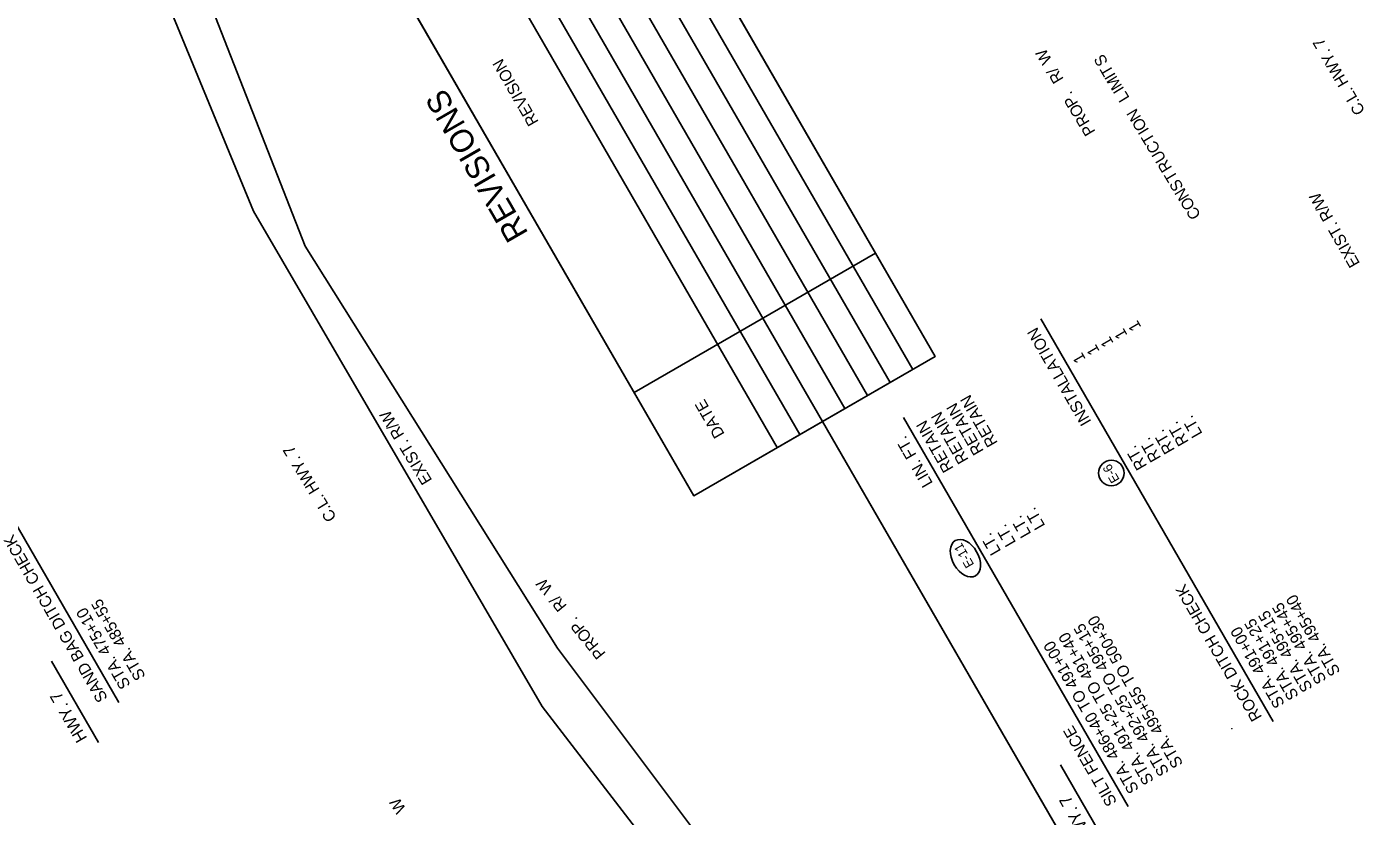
# Model space of a CAD drawing. Extents: x 956270 to 957915, y 1920520 to 1922423.
# Drawn here: x 956617 to 957310, y 1921329 to 1921739 of the extents above; entities that cross this region are included whole.
import ezdxf

# ---------------------------------------------------------------- set-up
doc = ezdxf.new("R2010")
doc.units = 0
for name, color, linetype in [('1', 7, 'Continuous'), ('44', 7, 'Continuous'), ('Default', 7, 'Continuous'), ('NO PLOT', 7, 'Continuous'), ('R_Draft', 7, 'Continuous'), ('S_MSC_PT_SYM', 7, 'Continuous')]:
    doc.layers.add(name, color=color, linetype=linetype)

msp = doc.modelspace()

# ---------------------------------------------------------------- linework, layer by layer
at = {"layer": '1'}
msp.add_line((957172.25, 1921286.08), (957029.16, 1921533.92), dxfattribs=at)
msp.add_circle((957178.89, 1921507.22), 6.61, dxfattribs=at)
msp.add_ellipse((957103.26, 1921463.06), major_axis=(-5.26, 9.11), ratio=0.638788, dxfattribs=at)
at = {"layer": '44'}
for p, q in [((956664.65, 1921388.23), (956544.14, 1921596.95)), ((957262.76, 1921378.39), (957142.26, 1921587.11)), ((957187.63, 1921334.37), (957071.23, 1921535.98)), ((956654.02, 1921367.45), (956629.6, 1921409.75)), ((957177, 1921313.59), (957152.58, 1921355.88))]:
    msp.add_line(p, q, dxfattribs=at)
at = {"layer": 'Default'}
for p, q in [((957087.62, 1921567.67), (956875.12, 1921935.73)), ((957075.93, 1921560.92), (956863.43, 1921928.98)), ((957064.24, 1921554.17), (956851.74, 1921922.23)), ((957052.55, 1921547.42), (956840.05, 1921915.48)), ((957040.85, 1921540.67), (956828.35, 1921908.73)), ((957040.85, 1921540.67), (956828.35, 1921908.73)), ((957029.16, 1921533.92), (956816.66, 1921901.98)), ((957017.47, 1921527.17), (956804.97, 1921895.23)), ((957005.78, 1921520.42), (956793.28, 1921888.48)), ((956962.48, 1921495.42), (956749.98, 1921863.48)), ((956931.57, 1921548.95), (957056.71, 1921621.2)), ((956962.48, 1921495.42), (957087.62, 1921567.67))]:
    msp.add_line(p, q, dxfattribs=at)
at = {"layer": 'NO PLOT'}
for points in [[(957915.18, 1921041.6), (957117.5, 1922423.23), (956666.17, 1922162.65), (956816.66, 1921901.98), (956875.12, 1921935.73), (957087.62, 1921567.67), (957029.16, 1921533.92), (957172.25, 1921286.08), (957225.74, 1921316.96), (957397.07, 1921020.21), (957343.58, 1920989.33), (957463.85, 1920781.02)], [(957915.18, 1921041.6), (957117.5, 1922423.23), (956666.17, 1922162.65), (956816.66, 1921901.98), (956875.12, 1921935.73), (957087.62, 1921567.67), (957029.16, 1921533.92), (957172.25, 1921286.08), (957225.74, 1921316.96), (957397.07, 1921020.21), (957343.58, 1920989.33), (957463.85, 1920781.02)], [(957915.18, 1921041.6), (957117.5, 1922423.23), (956666.17, 1922162.65), (956816.66, 1921901.98), (956875.12, 1921935.73), (957087.62, 1921567.67), (957029.16, 1921533.92), (957172.25, 1921286.08), (957225.74, 1921316.96), (957397.07, 1921020.21), (957343.58, 1920989.33), (957463.85, 1920781.02)], [(957915.18, 1921041.6), (957117.5, 1922423.23), (956666.17, 1922162.65), (956816.66, 1921901.98), (956875.12, 1921935.73), (957087.62, 1921567.67), (957029.16, 1921533.92), (957172.25, 1921286.08), (957225.74, 1921316.96), (957397.07, 1921020.21), (957343.58, 1920989.33), (957463.85, 1920781.02)], [(957012.51, 1920520.44), (956420.48, 1921545.87), (956463.26, 1921570.57), (956365.36, 1921740.14), (956378, 1921747.44), (956270.25, 1921934.07), (956666.17, 1922162.65), (956816.66, 1921901.98), (956749.98, 1921863.48), (956962.48, 1921495.42), (957029.16, 1921533.92), (957172.25, 1921286.08), (957120.9, 1921256.43), (957292.23, 1920959.68), (957343.58, 1920989.33), (957463.85, 1920781.02)], [(957012.51, 1920520.44), (956420.48, 1921545.87), (956463.26, 1921570.57), (956365.36, 1921740.14), (956378, 1921747.44), (956270.25, 1921934.07), (956666.17, 1922162.65), (956816.66, 1921901.98), (956749.98, 1921863.48), (956962.48, 1921495.42), (957029.16, 1921533.92), (957172.25, 1921286.08), (957120.9, 1921256.43), (957292.23, 1920959.68), (957343.58, 1920989.33), (957463.85, 1920781.02)], [(957012.51, 1920520.44), (956420.48, 1921545.87), (956463.26, 1921570.57), (956365.36, 1921740.14), (956378, 1921747.44), (956270.25, 1921934.07), (956666.17, 1922162.65), (956816.66, 1921901.98), (956749.98, 1921863.48), (956962.48, 1921495.42), (957029.16, 1921533.92), (957172.25, 1921286.08), (957120.9, 1921256.43), (957292.23, 1920959.68), (957343.58, 1920989.33), (957463.85, 1920781.02)], [(957012.51, 1920520.44), (956420.48, 1921545.87), (956463.26, 1921570.57), (956365.36, 1921740.14), (956378, 1921747.44), (956270.25, 1921934.07), (956666.17, 1922162.65), (956816.66, 1921901.98), (956749.98, 1921863.48), (956962.48, 1921495.42), (957029.16, 1921533.92), (957172.25, 1921286.08), (957120.9, 1921256.43), (957292.23, 1920959.68), (957343.58, 1920989.33), (957463.85, 1920781.02)]]:
    msp.add_lwpolyline(points, close=True, dxfattribs=at)
msp.add_lwpolyline([(956978.43, 1921300.96), (956891.96, 1921416.34), (956761.21, 1921624.84), (956685.68, 1921817.75), (956598.64, 1922001.42), (956569.16, 1922006.84), (956549.42, 1922003.64), (956496.56, 1922078), (956484.6, 1922065.05), (956487.74, 1922034.93), (956520.15, 1921988.76), (956538.43, 1921986.13), (956552.84, 1921975.42), (956577.89, 1921905.71), (956667.63, 1921797.4), (956675.52, 1921785.98), (956734.33, 1921642.98), (956883.87, 1921386.21), (956963.43, 1921282.81)], dxfattribs=at)
at = {"layer": 'S_MSC_PT_SYM'}
msp.add_lwpolyline([(957241.32, 1921374.69), (957241.32, 1921374.74), (957241.32, 1921374.69), (957241.27, 1921374.69), (957241.32, 1921374.69), (957241.32, 1921374.64), (957241.32, 1921374.69), (957241.37, 1921374.69)], dxfattribs=at)

# ---------------------------------------------------------------- texts
at = {"layer": '1'}
for s, rotation, p in [('E-6 ', 120, (957183.29, 1921503.76)), ('E-11', 119.99998, (957107.91, 1921459.74))]:
    msp.add_text(s, height=4.8, rotation=rotation, dxfattribs=at).set_placement(p)
at = {"layer": '44'}
for s, height, rotation, p in [('INSTALLATION', 6, 120, (957168.69, 1921533.83)), ('1', 6, 120, (957187.38, 1921578.74)), ('1', 6, 120, (957194.56, 1921582.89)), ('1', 6, 120, (957180.2, 1921574.6)), ('1', 6, 120, (957165.77, 1921566.27)), ('1', 6, 120, (957172.98, 1921570.43)), ('RETAIN', 6, 119.99998, (957120.18, 1921522.85)), ('RETAIN', 6, 119.99998, (957112.95, 1921518.68)), ('RETAIN', 6, 119.99998, (957097.31, 1921509.65)), ('RETAIN', 6, 119.99998, (957105.06, 1921514.12)), ('RT.', 6, 120, (957219.15, 1921523.38)), ('LT.', 6, 120, (957226.26, 1921527.65)), ('LIN. FT.', 6, 119.99998, (957086.55, 1921501.93)), ('RT.', 6, 120, (957211.97, 1921519.23)), ('RT.', 6, 120, (957197.54, 1921510.9)), ('RT.', 6, 120, (957204.76, 1921515.06)), ('LT.', 6, 119.99998, (957137.53, 1921475.77)), ('LT.', 6, 119.99998, (957144.76, 1921479.94)), ('LT.', 6, 119.99998, (957129.64, 1921471.22)), ('SAND BAG DITCH CHECK', 6, 120, (956659, 1921390.5)), ('LT.', 6, 119.99998, (957121.89, 1921466.74)), ('ROCK DITCH CHECK', 6, 120, (957257.11, 1921380.67)), ('STA. 495+40', 6, 120, (957297.75, 1921404.13)), ('STA. 475+10', 6, 120, (956670.84, 1921397.34)), ('STA. 485+55', 6, 120, (956678.63, 1921401.84)), ('STA. 495+45', 6, 120, (957290.57, 1921399.98)), ('STA. 495+55 TO 500+30', 6, 119.99998, (957216.24, 1921356.42)), ('STA. 491+25', 6, 120, (957276.17, 1921391.67)), ('STA. 495+15', 6, 120, (957283.39, 1921395.83)), ('STA. 491+25 TO 491+40', 6, 119.99998, (957201.13, 1921347.7)), ('STA. 492+25 TO 495+15', 6, 119.99998, (957209.01, 1921352.25)), ('STA. 491+00', 6, 120, (957268.95, 1921387.5)), ('STA. 486+40 TO 491+00', 6, 119.99998, (957193.38, 1921343.22)), ('HWY. 7', 6.25, 120, (956648.33, 1921369.76)), ('SILT FENCE      ', 6, 119.99998, (957181.98, 1921336.64)), ('HWY. 7', 6.25, 120, (957171.31, 1921315.89))]:
    msp.add_text(s, height=height, rotation=rotation, dxfattribs=at).set_placement(p)
at = {"layer": 'Default'}
for s, height, p in [('REVISION', 6, (956882.3, 1921689.29)), ('REVISIONS', 12, (956876.99, 1921631.48)), ('DATE', 6, (956978.64, 1921527.43))]:
    msp.add_text(s, height=height, rotation=120, dxfattribs=at).set_placement(p)
at = {"layer": 'R_Draft'}
for s, rotation, p in [('C.L. HWY. 7', 120.29751, (957310.57, 1921694.94)), ('W', 121.18992, (957148.36, 1921721.3)), ('S', 120.26716, (957177.35, 1921720.24)), ('/', 121.18992, (957151.4, 1921716.29)), ('R', 121.18992, (957154.33, 1921711.44)), ('T', 120.26716, (957180.3, 1921715.18)), ('I', 120.26716, (957181.3, 1921713.47)), ('M', 121.40689, (957184.67, 1921708)), ('I', 121.40689, (957185.71, 1921706.31)), ('P', 121.18992, (957161.89, 1921698.95)), ('.', 121.18992, (957158.96, 1921703.8)), ('L', 121.31637, (957188.51, 1921701.71)), ('O', 121.18992, (957164.93, 1921693.94)), ('R', 121.18992, (957167.86, 1921689.09)), ('N', 121.01897, (957194.54, 1921691.72)), ('P', 121.18992, (957170.8, 1921684.24)), ('O', 121.01897, (957197.56, 1921686.7)), ('I', 121.36248, (957198.61, 1921685.01)), ('T', 121.36248, (957201.66, 1921680.01)), ('C', 120.9351, (957204.57, 1921675.14)), ('U', 120.78654, (957207.51, 1921670.19)), ('R', 121.73269, (957210.53, 1921665.39)), ('T', 120.85683, (957213.56, 1921660.38)), ('S', 120.85683, (957216.47, 1921655.51)), ('N', 121.93286, (957219.45, 1921650.69)), ('EXIST. R/W', 119.9486, (957307.86, 1921615.9)), ('O', 121.93286, (957222.55, 1921645.72)), ('C', 121.15736, (957225.48, 1921640.86)), ('EXIST. R/W', 121.48809, (956827.1, 1921503.48)), ('C.L. HWY. 7', 121.35452, (956777.58, 1921484.17)), ('W', 129.14741, (956889.75, 1921447.33)), ('/', 129.14741, (956893.45, 1921442.79)), ('R', 129.14741, (956897.02, 1921438.39)), ('.', 129.14741, (956902.66, 1921431.46)), ('P', 129.14741, (956906.24, 1921427.07)), ('O', 129.14741, (956909.94, 1921422.52)), ('R', 129.14741, (956913.52, 1921418.13)), ('P', 129.14741, (956917.1, 1921413.73)), ('W', 122.05288, (956813.6, 1921333.05))]:
    msp.add_text(s, height=6, rotation=rotation, dxfattribs=at).set_placement(p)

doc.saveas('drawing.dxf')
